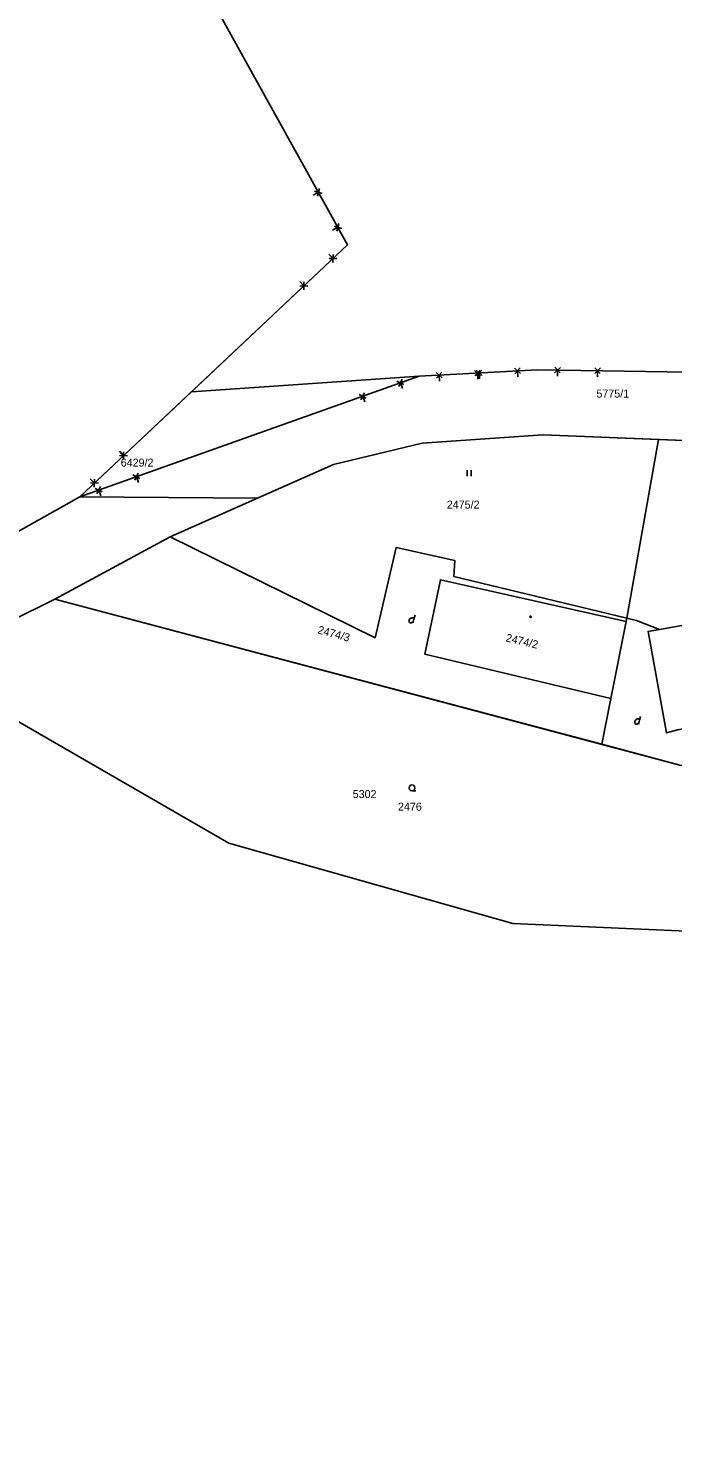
# Model space of a CAD drawing. Extents: x -439750 to -439180, y -1258684 to -1258308.
# Drawn here: x -439630.4 to -439598.2, y -1258510.9 to -1258440.1 of the extents above; entities that cross this region are included whole.
import ezdxf

# ---------------------------------------------------------------- set-up
doc = ezdxf.new("R2010")
doc.units = 0
doc.layers.add('KATASTER', color=7, linetype='Continuous')
doc.layers.add('UOV', color=7, linetype='Continuous')

# ---------------------------------------------------------------- blocks, each defined once
blk = doc.blocks.new('304')
blk.add_lwpolyline([(0, 0), (-0.38, 0.1), (-0.65, 0.37), (-0.75, 0.74), (-0.65, 1.11), (-0.38, 1.38), (-0.01, 1.48), (0.36, 1.38), (0.63, 1.11), (0.73, 0.73), (0.63, 0.35), (0.36, 0.08), (-0.02, -0.02), (0.98, -0.02)])
blk = doc.blocks.new('DVUR')
blk.add_line((0.63, 0.99), (0.9, 1.89))
blk.add_lwpolyline([(0.45, 0), (0.45, 0.27), (0.63, 0.99), (0.54, 1.17), (0.36, 1.26), (0.09, 1.26), (-0.18, 1.17), (-0.36, 0.99), (-0.54, 0.72), (-0.54, 0.36), (-0.45, 0.09), (-0.27, 0), (0, 0), (0.18, 0.09), (0.45, 0.27)])
blk = doc.blocks.new('402')
blk.add_lwpolyline([(0.09, 0.15), (0.18, 0), (0.09, -0.15), (-0.09, -0.15), (-0.18, 0), (-0.09, 0.15), (0.09, 0.15)])
blk = doc.blocks.new('306')
for p, q in [((-0.5, 1.5), (-0.5, 0)), ((0.5, 0), (0.5, 1.5))]:
    blk.add_line(p, q)
blk = doc.blocks.new('2072')
for p, q in [((-4.3, 0.7), (-5.7, -0.7)), ((-5.7, 0.7), (-4.3, -0.7)), ((-5, 0), (-5, -1.5)), ((4.3, 0.7), (5.7, -0.7)), ((5.7, 0.7), (4.3, -0.7)), ((5, 0), (5, -1.5))]:
    blk.add_line(p, q)

msp = doc.modelspace()

# ---------------------------------------------------------------- linework, layer by layer
at = {"layer": 'KATASTER'}
for points in [[(-439680.32, -1258364.89), (-439664.32, -1258378.2), (-439607.94, -1258413.98), (-439588.39, -1258414.26), (-439581.78, -1258408.62), (-439578.76, -1258414.75), (-439570.17, -1258432.21), (-439566.51, -1258439.64), (-439567.09, -1258440.4), (-439572.34, -1258446.7), (-439579.1, -1258452.12), (-439586.76, -1258455.52), (-439594.1, -1258457.31), (-439604.91, -1258457.14), (-439610.82, -1258457.46), (-439627.78, -1258463.49), (-439614.4, -1258450.89), (-439625.47, -1258430.92), (-439655.75, -1258405.12), (-439680.64, -1258393.46)], [(-439529.05, -1258372.98), (-439583.01, -1258405.44), (-439581.78, -1258408.62), (-439578.76, -1258414.75), (-439570.17, -1258432.21), (-439566.51, -1258439.64), (-439567.09, -1258440.4), (-439572.34, -1258446.7), (-439579.1, -1258452.12), (-439586.76, -1258455.52), (-439594.1, -1258457.31), (-439604.91, -1258457.14), (-439610.82, -1258457.46), (-439627.78, -1258463.49), (-439614.4, -1258450.89), (-439625.47, -1258430.92), (-439655.75, -1258405.12), (-439680.64, -1258393.46)], [(-439680.64, -1258393.46), (-439655.75, -1258405.12), (-439625.47, -1258430.92), (-439614.4, -1258450.89), (-439627.78, -1258463.49), (-439610.82, -1258457.46), (-439604.91, -1258457.14), (-439594.1, -1258457.31), (-439586.76, -1258455.52), (-439579.1, -1258452.12), (-439572.34, -1258446.7), (-439567.09, -1258440.4), (-439566.51, -1258439.64), (-439570.17, -1258432.21), (-439578.76, -1258414.75), (-439581.78, -1258408.62), (-439583.01, -1258405.44), (-439529.05, -1258372.98)], [(-439660.49, -1258516.44), (-439665.91, -1258502.4), (-439666.82, -1258496.88), (-439665.48, -1258490.84), (-439662.74, -1258486.44), (-439657.56, -1258481.06), (-439653.51, -1258478.38), (-439649.29, -1258475.58), (-439627.78, -1258463.49), (-439610.82, -1258457.46), (-439604.91, -1258457.14), (-439594.1, -1258457.31), (-439586.76, -1258455.52), (-439579.1, -1258452.12), (-439572.34, -1258446.7), (-439567.09, -1258440.4), (-439566.51, -1258439.64), (-439564.85, -1258437.53), (-439556.57, -1258427.01), (-439547.65, -1258418.05), (-439537.73, -1258410.35)], [(-439536.05, -1258413.64), (-439546.05, -1258421.31), (-439554.71, -1258430.36), (-439570.11, -1258449.98), (-439574.47, -1258453.63), (-439580.2, -1258456.85), (-439586.86, -1258459.56), (-439593.42, -1258460.84), (-439598.86, -1258460.62), (-439604.63, -1258460.39), (-439610.67, -1258460.8), (-439615.1, -1258461.87), (-439623.26, -1258465.49), (-439629.03, -1258468.61), (-439635.72, -1258471.93), (-439658.88, -1258489.54), (-439659.88, -1258488.91), (-439662.11, -1258495.3), (-439662.28, -1258501.2), (-439658.45, -1258512.88)]]:
    msp.add_lwpolyline(points, dxfattribs=at)
for points in [[(-439654.95, -1258434.81), (-439653.48, -1258436.02), (-439639.58, -1258447.44), (-439637.04, -1258443.88), (-439631.52, -1258437.16), (-439625.47, -1258430.92), (-439614.4, -1258450.89), (-439627.78, -1258463.49), (-439649.29, -1258475.58), (-439651.22, -1258464.92)], [(-439580.2, -1258456.85), (-439574.47, -1258453.63), (-439570.11, -1258449.98), (-439560.37, -1258460.62), (-439584.69, -1258466.8), (-439584.46, -1258467.67), (-439585.51, -1258467.75), (-439585.89, -1258465.59), (-439591.29, -1258466.55), (-439590.9, -1258468.71), (-439598.81, -1258470.12), (-439599.97, -1258469.68), (-439600.45, -1258469.56), (-439598.86, -1258460.62), (-439593.42, -1258460.84), (-439586.86, -1258459.56)], [(-439604.63, -1258460.39), (-439598.86, -1258460.62), (-439600.45, -1258469.56), (-439609.09, -1258467.48), (-439609.04, -1258466.68), (-439611.98, -1258466.03), (-439613.02, -1258470.54), (-439623.26, -1258465.49), (-439615.1, -1258461.87), (-439610.67, -1258460.8)], [(-439623.26, -1258465.49), (-439613.02, -1258470.54), (-439611.98, -1258466.03), (-439609.04, -1258466.68), (-439609.09, -1258467.48), (-439600.45, -1258469.56), (-439600.48, -1258469.73), (-439609.76, -1258467.64), (-439610.54, -1258471.35), (-439601.25, -1258473.57), (-439601.7, -1258475.86), (-439629.03, -1258468.61)], [(-439591.29, -1258466.55), (-439585.89, -1258465.59), (-439585.51, -1258467.75), (-439584.46, -1258467.67), (-439584.35, -1258468.11), (-439583.22, -1258473.09), (-439588.76, -1258473.52), (-439588.4, -1258476.16), (-439592.84, -1258476.8), (-439593.1, -1258474.29), (-439597.91, -1258475.14), (-439598.47, -1258475.29), (-439599.38, -1258470.22), (-439598.81, -1258470.12), (-439590.9, -1258468.71)], [(-439601.25, -1258473.57), (-439610.54, -1258471.35), (-439609.76, -1258467.64), (-439600.48, -1258469.73)], [(-439635.72, -1258471.93), (-439629.03, -1258468.61), (-439601.7, -1258475.86), (-439597.79, -1258476.9), (-439591.18, -1258477.49), (-439591.03, -1258485.49), (-439606.15, -1258484.83), (-439620.34, -1258480.81)], [(-439583.22, -1258473.09), (-439583.13, -1258475.1), (-439591.18, -1258477.49), (-439597.79, -1258476.9), (-439601.7, -1258475.86), (-439601.25, -1258473.57), (-439600.48, -1258469.73), (-439600.45, -1258469.56), (-439599.97, -1258469.68), (-439598.81, -1258470.12), (-439599.38, -1258470.22), (-439598.47, -1258475.29), (-439597.91, -1258475.14), (-439593.1, -1258474.29), (-439592.84, -1258476.8), (-439588.4, -1258476.16), (-439588.76, -1258473.52)], [(-439658.88, -1258489.54), (-439635.72, -1258471.93), (-439620.34, -1258480.81), (-439606.15, -1258484.83), (-439591.03, -1258485.49), (-439564.69, -1258504.32), (-439589.36, -1258506.21), (-439597.08, -1258522.38), (-439597.45, -1258561.13), (-439640.46, -1258538.63)]]:
    msp.add_lwpolyline(points, close=True, dxfattribs=at)
at = {"layer": 'UOV'}
for points in [[(-439554.71, -1258430.36), (-439570.11, -1258449.98), (-439574.47, -1258453.63), (-439580.2, -1258456.85), (-439586.86, -1258459.56), (-439593.42, -1258460.84), (-439604.63, -1258460.39), (-439610.67, -1258460.8), (-439615.1, -1258461.87), (-439618.9, -1258463.55), (-439627.78, -1258463.49), (-439610.82, -1258457.46), (-439604.91, -1258457.14), (-439594.1, -1258457.31), (-439586.76, -1258455.52), (-439579.1, -1258452.12), (-439572.34, -1258446.7), (-439567.09, -1258440.4), (-439566.51, -1258439.64)], [(-439566.51, -1258439.64), (-439567.09, -1258440.4), (-439572.34, -1258446.7), (-439579.1, -1258452.12), (-439586.76, -1258455.52), (-439594.1, -1258457.31), (-439604.91, -1258457.14), (-439610.82, -1258457.46), (-439622.2, -1258458.24), (-439614.4, -1258450.89), (-439625.47, -1258430.92)]]:
    msp.add_lwpolyline(points, dxfattribs=at)
for points in [[(-439627.78, -1258463.49), (-439622.2, -1258458.24), (-439610.82, -1258457.46)], [(-439649.29, -1258475.58), (-439627.78, -1258463.49), (-439618.9, -1258463.55), (-439623.26, -1258465.49), (-439629.03, -1258468.61), (-439635.72, -1258471.93), (-439658.88, -1258489.54), (-439659.88, -1258488.91), (-439662.11, -1258495.3), (-439662.28, -1258501.2), (-439658.45, -1258512.88), (-439640.46, -1258538.63), (-439645.84, -1258537.45), (-439648.8, -1258533.92), (-439660.49, -1258516.44), (-439665.91, -1258502.4), (-439666.82, -1258496.88), (-439665.48, -1258490.84), (-439662.74, -1258486.44), (-439657.56, -1258481.06), (-439653.51, -1258478.38)], [(-439629.03, -1258468.61), (-439597.79, -1258476.9), (-439591.18, -1258477.49), (-439591.03, -1258485.49), (-439606.15, -1258484.83), (-439620.34, -1258480.81), (-439635.72, -1258471.93)]]:
    msp.add_lwpolyline(points, close=True, dxfattribs=at)

# ---------------------------------------------------------------- block references
at = {"layer": 'KATASTER'}
for p, xscale, yscale, rotation in [((-439615.37, -1258449.141), 0.20000000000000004, 0.2, -60.97332699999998), ((-439615.856, -1258452.261), 0.2, 0.20000000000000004, -136.71834700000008), ((-439608.823, -1258457.352), 0.2, 0.20000000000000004, 3.0939720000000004), ((-439606.907, -1258457.248), 0.2, 0.20000000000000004, 3.0939720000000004), ((-439602.91, -1258457.171), 0.2, 0.20000000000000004, -0.9273500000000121), ((-439612.704, -1258458.13), 0.2, 0.20000000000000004, 19.595157), ((-439626.324, -1258462.119), 0.2, 0.20000000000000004, -136.71834700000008), ((-439625.896, -1258462.82), 0.2, 0.20000000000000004, 19.595157)]:
    msp.add_blockref('2072', p, dxfattribs=dict(at, xscale=xscale, yscale=yscale, rotation=rotation))
at = {"layer": 'KATASTER', "xscale": 0.2, "yscale": 0.20000000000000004}
for name, p in [('306', (-439608.32, -1258462.45)), ('DVUR', (-439611.21, -1258469.79)), ('402', (-439605.26, -1258469.49)), ('DVUR', (-439599.94, -1258474.85)), ('304', (-439611.18, -1258478.19))]:
    msp.add_blockref(name, p, dxfattribs=at)

# ---------------------------------------------------------------- texts
at = {"layer": 'KATASTER'}
for s, p in [('5775/1', (-439601.965, -1258458.53)), ('2475/2', (-439609.442, -1258464.08)), ('2476', (-439611.882, -1258479.18))]:
    msp.add_text(s, height=0.4, dxfattribs=at).set_placement(p)
for s, rotation, p in [('2474/3', 344.634, (-439615.926, -1258470.308)), ('2474/2', 346.697, (-439606.523, -1258470.712))]:
    msp.add_text(s, height=0.4, rotation=rotation, dxfattribs=at).set_placement(p)
at = {"layer": 'UOV'}
for s, p in [('6429/2', (-439625.736, -1258461.98)), ('5302', (-439614.144, -1258478.55))]:
    msp.add_text(s, height=0.4, dxfattribs=at).set_placement(p)

doc.saveas('drawing.dxf')
